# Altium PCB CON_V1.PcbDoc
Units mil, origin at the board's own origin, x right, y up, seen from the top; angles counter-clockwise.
Board outline 3920 x 2000 mil, 2 copper layers (Top Layer, Bottom Layer); 11 components, 18 nets, 80 pads, 4 vias.
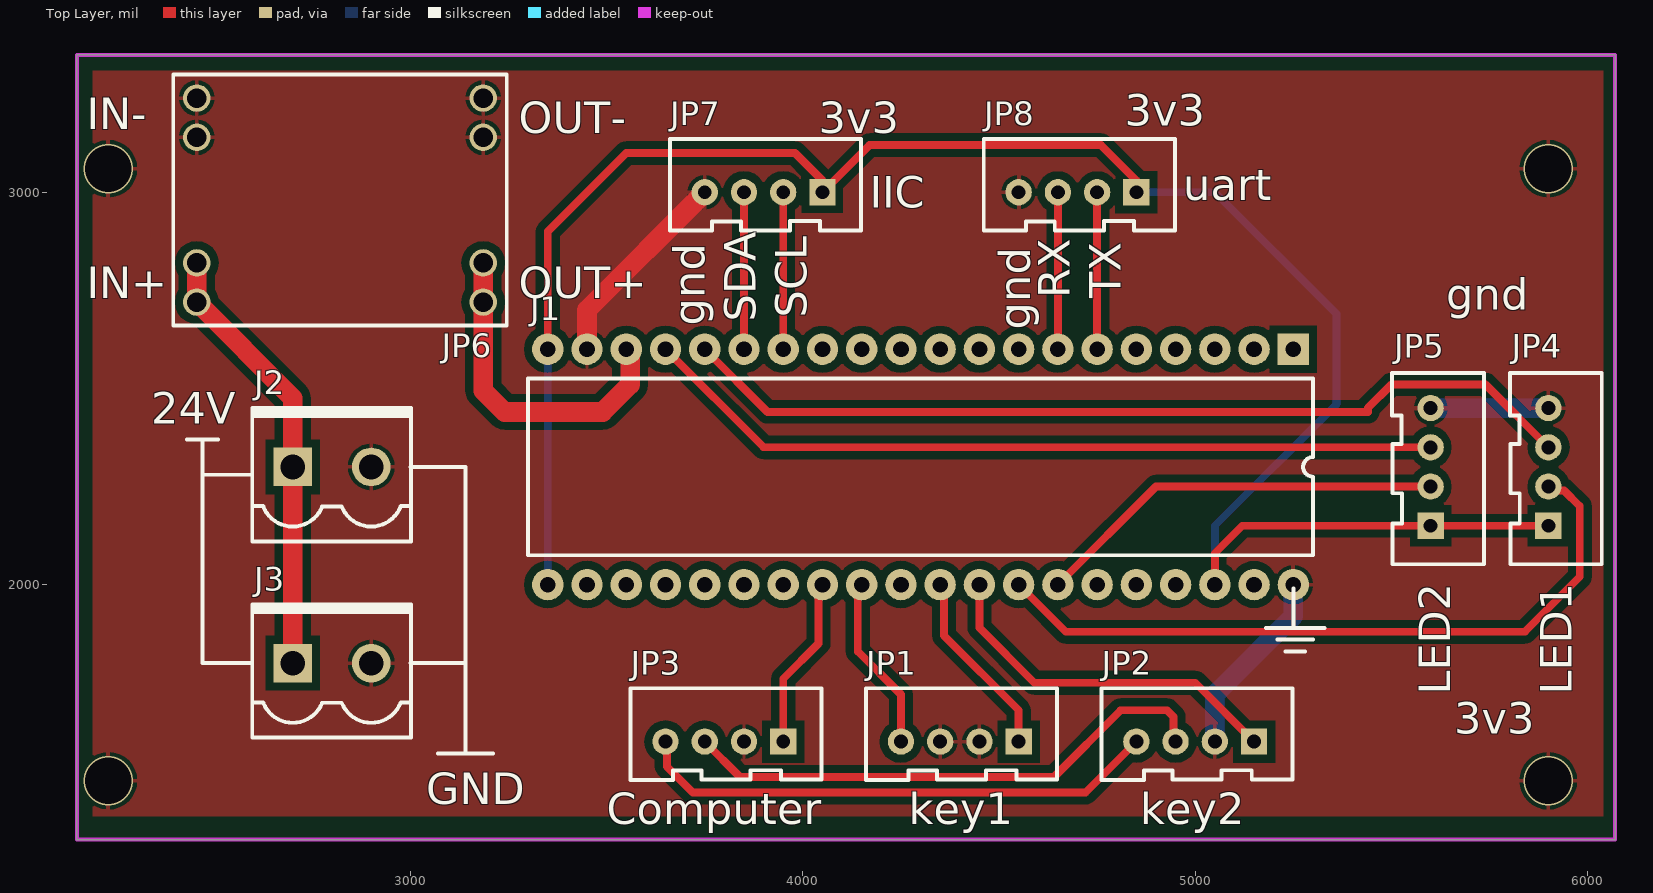
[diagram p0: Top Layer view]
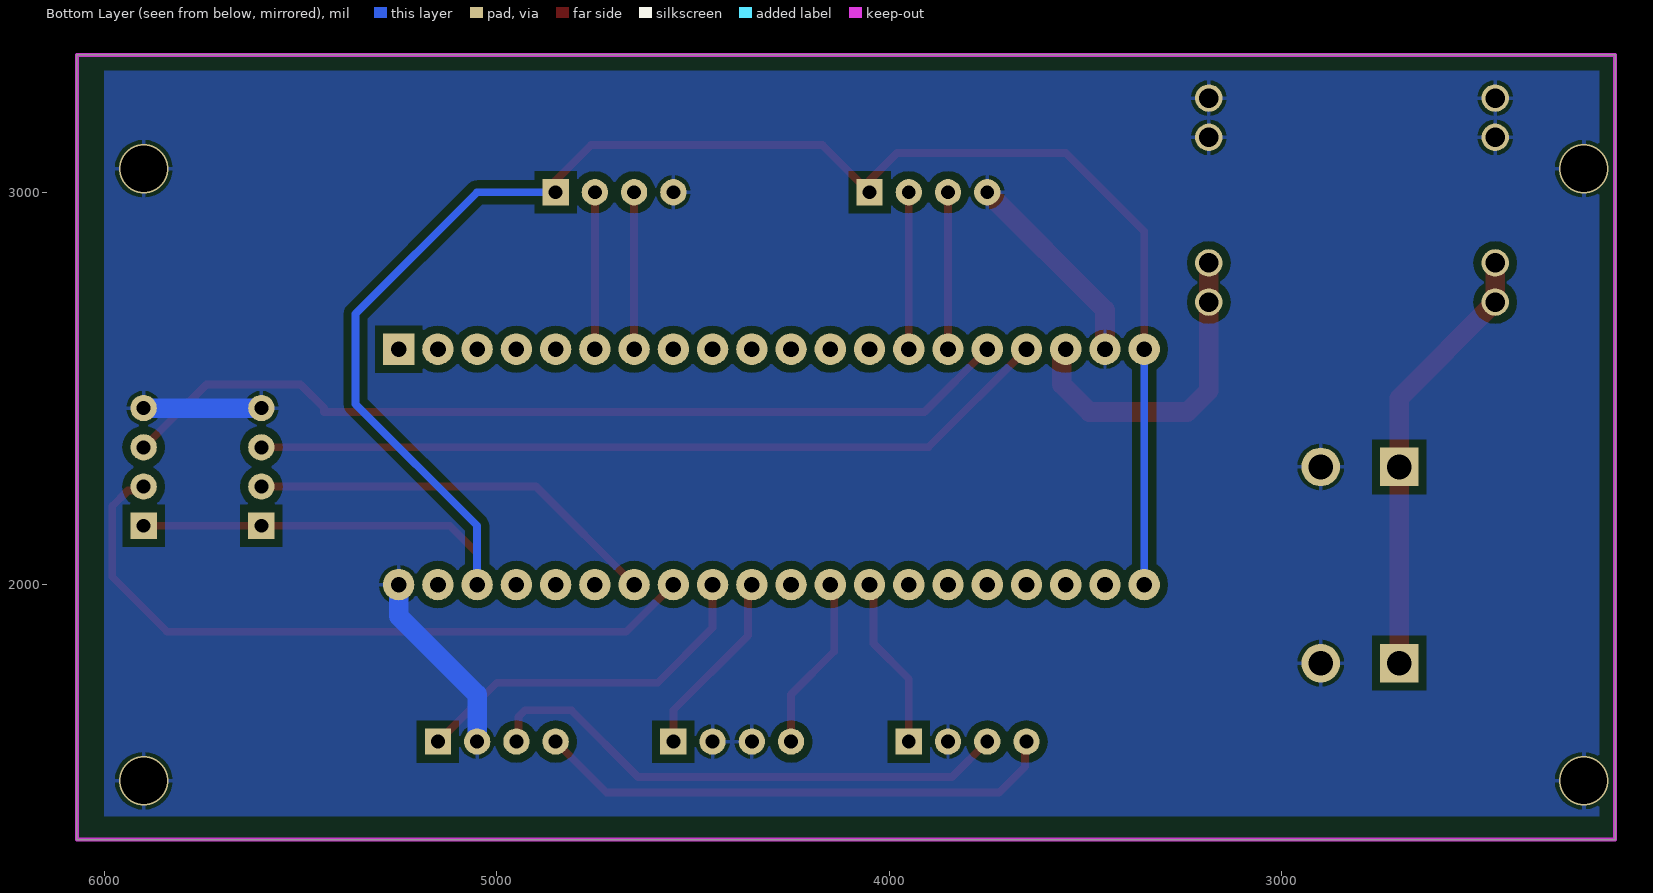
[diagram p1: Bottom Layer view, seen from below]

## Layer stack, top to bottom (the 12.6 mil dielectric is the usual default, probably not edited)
Top Solder: solder mask 0.4, Solder Resist, Dk 3.5
Top Layer: signal copper 1.4
Dielectric 1: dielectric 12.6, FR-4, Dk 4.8
Bottom Layer: signal copper 1.4
Bottom Solder: solder mask 0.4, Solder Resist, Dk 3.5

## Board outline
2150,1350 2150,3350 6070,3350 6070,1350

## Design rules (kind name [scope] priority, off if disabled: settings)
Clearance [All] p1: gap=10 ignorepadtopadclearanceinfootprint=FALSE except(0: Arc-Hole Track-Hole SMDPad-Hole THPad-Hole Via-Hole Fill-Hole Poly-Hole Region-Hole Text-Hole; 20: Arc-Fill Arc-Poly Arc-Region Track-Fill Track-Poly Track-Region SMDPad-Fill SMDPad-Poly SMDPad-Region THPad-Fill THPad-Poly THPad-Region Via-Fill Via-Poly Via-Region Fill-Fill Fill-Poly Fill-Region Poly-Poly Poly-Region Region-Region)
PlaneClearance [All] p1: clearance=30
PolygonConnect [All] p1: connectstyle=Relief reliefconductorwidth=10 reliefentries=4 polygonreliefangle="90 Angle" airgapwidth=10
RoutingVias [All] p1: holewidth=28 width=50 viastyle="Through Hole" minholewidth=28 minwidth=50 maxholewidth=28 maxwidth=50
SolderMaskExpansion [All] p1: expansion=4
Width [All] p1: maxlimit=100 minlimit=10 preferedwidth=20 minimp=50.000000 maximp=50.000000 favimp=50.000000
29 further rules are at their usual default settings.

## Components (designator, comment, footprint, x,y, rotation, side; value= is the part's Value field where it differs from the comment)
J1 "C8T6" C8T6 4300,2300 r270 top
J2 "CON2" KF2EDGK5.08-LI-2P 2800,2300 r0 top
J3 "CON2" KF2EDGK5.08-LI-2P 2800,1800 r0 top
JP1 "HDR-1X4" XH2.54-LI-4P 4400,1600 r180 top
JP2 "HDR-1X4" XH2.54-LI-4P 5000,1600 r180 top
JP3 "HDR-1X4" XH2.54-LI-4P 3800,1600 r180 top
JP4 "HDR-1X4" XH2.54-LI-4P 5900,2300 r90 top
JP5 "HDR-1X4" XH2.54-LI-4P 5600,2300 r90 top
JP6 "Stereye buck module" "Stereye buck module" 2455.47,2720 r0 top
JP7 "HDR-1X4" XH2.54-LI-4P 3900,3000 r180 top
JP8 "HDR-1X4" XH2.54-LI-4P 4700,3000 r180 top

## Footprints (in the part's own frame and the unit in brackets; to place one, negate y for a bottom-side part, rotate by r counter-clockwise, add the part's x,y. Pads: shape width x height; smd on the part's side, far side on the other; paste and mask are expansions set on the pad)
C8T6 [mil]
  rect 80x80 hole 40: 1(-300,950)
  round 80 hole 40: 2(-300,850) 3(-300,750) 4(-300,650) 5(-300,550) 6(-300,450) 7(-300,350) 8(-300,250) 9(-300,150) 10(-300,50) 11(-300,-50) 12(-300,-150) 13(-300,-250) 14(-300,-350) 15(-300,-450) 16(-300,-550) 17(-300,-650) 18(-300,-750) 19(-300,-850) 20(-300,-950) 21(300,-950) 22(300,-850) 23(300,-750) 24(300,-650) 25(300,-550) 26(300,-450) 27(300,-350) 28(300,-250) 29(300,-150) 30(300,-50) 31(300,50) 32(300,150) 33(300,250) 34(300,350) 35(300,450) 36(300,550) 37(300,650) 38(300,750) 39(300,850) 40(300,950)
  silkscreen extent -225,-1000 225,1000
KF2EDGK5.08-LI-2P [mm] "立插端子"
  rect 2.5x2.5 hole 1.6: 1(-2.54,0)
  round 2.5 hole 1.6: 2(2.54,0)
  silkscreen extent -5.16,-4.83 5.13,3.81, body extent -5.08,-4.75 5.08,3.75, height 11.25
"Stereye buck module" [mil]
  round 70 hole 50: 1(0,520) 2(0,420) 3(0,100) 4(0,0) 5(730,0) 6(730,100) 7(730,420) 8(730,520)
  silkscreen extent -60,-60 790,580
XH2.54-LI-4P [mm] "接插件，4P  淘宝ID:黄晶宝石   店铺网址:https://shop463601444.taobao.com"
  rect 1.7x1.7 hole 0.9: 1(-3.81,0)
  round 1.7 hole 0.9: 2(-1.27,0) 3(1.27,0) 4(3.81,0)
  silkscreen extent -6.3,-3.45 6.07,2.49, body extent -6.31,-3.3 6.31,2.4, height 7.03

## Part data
J1: "C8T6转接"
JP1 JP2 JP3 JP4 JP5 JP7 JP8: library part "Header 4", "4P接插件"

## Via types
v1: diameter 125.98, hole 118.11, Top Layer to Bottom Layer, 4 vias

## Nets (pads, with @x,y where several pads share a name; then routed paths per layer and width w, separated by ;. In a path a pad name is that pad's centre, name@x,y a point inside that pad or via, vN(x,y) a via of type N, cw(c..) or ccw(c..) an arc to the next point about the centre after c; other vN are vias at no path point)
3V3: J1.20 J1.21 J1.38 JP4.1 JP5.1 JP7.1 JP8.1 | length 5074.6
  Top Layer w20: J1.20 3350,2900 3550,3100 3980,3100 4050,3030 JP7.1 4170,3120 4760,3120 4850,3030 JP8.1 ; J1.38 5050,2080 5120,2150 JP5.1 JP4.1
  Bottom Layer w20: J1.21 J1.20 ; JP8.1 5050,3000 5360,2690 5360,2460 5050,2150 J1.38
24V: J2.1 J3.1 JP6.3 JP6.4 | length 1121.3
  Top Layer w50: JP6.3 JP6.4 2700,2475.47 J2.1 J3.1
+5: J1.18 JP6.5 JP6.6 | length 845.7
  Top Layer w50: JP6.6 JP6.5 3185.47,2494.53 3240,2440 3490,2440 3560,2510 3560,2590 J1.18
GND: J1.19 J1.40 J2.2 J3.2 JP1.2 JP1.3 JP2.2 JP3.2 JP4.4 JP5.4 JP6.1 JP6.2 JP6.7 JP6.8 JP7.4 JP8.4 | length 1307.1
  Top Layer w50: J1.19 3450,2700 JP7.4
  Bottom Layer w50: JP2.2 5050,1720 5250,1920 J1.40 ; JP5.4 JP4.4
  other v1: 2230,1500 5900,1500 2230,3060 5900,3060
KEY1: J1.29 JP1.4 | length 449.7
  Top Layer w20: J1.29 4140,1990 4140,1830 4250,1720 JP1.4
KEY2: JP2.4 JP3.4 | length 1342.8
  Top Layer w20: JP3.4 3653.46,1596.54 3653.46,1536.54 3720,1470 4720,1470 JP2.4
KEY2_GND: JP2.3 JP3.3 | length 1375
  Top Layer w20: JP3.3 3840,1510 4640,1510 4810,1680 4928.28,1680 4944.82,1663.46 4944.82,1605.18 JP2.3
KEYLED1+: J1.31 JP1.1 | length 482.8
  Top Layer w20: J1.31 4360,1990 4360,1870 4550,1680 JP1.1
KEYLED2+: J1.32 JP2.1 | length 930.1
  Top Layer w20: J1.32 4450,1890 4590,1750 5000,1750 JP2.1
LED1G: J1.16 JP4.3 | length 2317.4
  Top Layer w20: J1.16 3910,2440 5440,2440 5440,2450 5500,2510 5740,2510 JP4.3
LED1R: J1.33 JP4.2 | length 1818.4
  Top Layer w20: J1.33 4670,1880 5840,1880 5980,2020 5980,2200 5940,2240 5910,2240 JP4.2
LED2G: J1.17 JP5.3 | length 2053.6
  Top Layer w20: J1.17 3900,2350 JP5.3
LED2R: J1.34 JP5.2 | length 1053.6
  Top Layer w20: J1.34 4900,2250 JP5.2
RX: J1.7 JP8.3 | length 400
  Top Layer w20: J1.7 JP8.3
SCL: J1.14 JP7.2 | length 400
  Top Layer w20: J1.14 JP7.2
SDA: J1.15 JP7.3 | length 400
  Top Layer w20: J1.15 JP7.3
TX: J1.6 JP8.2 | length 400
  Top Layer w20: J1.6 JP8.2
WAKE_UP: J1.28 JP3.1 | length 441.4
  Top Layer w20: JP3.1 3950,1760 4040,1850 4040,1990 J1.28
pads on no net: J1.1 J1.2 J1.3 J1.4 J1.5 J1.8 J1.9 J1.10 J1.11 J1.12 J1.13 J1.22 J1.23 J1.24 J1.25 J1.26 J1.27 J1.30 J1.35 J1.36 J1.37 J1.39

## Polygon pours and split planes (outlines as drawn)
GND on Top Layer "GND_L01_P000" (solid, remove dead copper, pour order 0): 2190,3310 2190,1410 6040,1410 6040,3310
GND on Bottom Layer "GND_L02_P002" (solid, remove dead copper, pour order 2): 2190,3310 2190,1410 6000,1410 6000,3310

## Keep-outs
Keep-Out Layer:
  the board outline again, w10

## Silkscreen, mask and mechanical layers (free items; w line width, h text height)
Top Overlay:
  lines w10: 2430,2370 2470,2370 ; 2470,2280 2596.85,2280 ; 2510,2370 2470,2370 ; 2590,1800 2470,1800 2470,2370 ; 3000,1800 3140,1800 ; 3000,2300 3140,2300 3140,1570 ; 3070,1570 3210,1570 ; 5180,1890 5330,1890 ; 5210,1860 5300,1860 ; 5230,1830 5280,1830 ; 5250,1890 5250,1990
  text "3v3" at 4820,3170 h80
  text "3v3" at 4040,3150 h80
  text "uart" at 4970,2980 h80
  text "IIC" at 4170,2960 h80
  text "RX" at 4680,2730 h80 r90
  text "TX" at 4810,2730 h80 r90
  text "gnd" at 5640,2700 h80
  text "SCL" at 4010,2680 h80 r90
  text "SDA" at 3880,2670 h80 r90
  text "gnd" at 3750,2660 h80 r90
  text "gnd" at 4580,2650 h80 r90
  text "24V" at 2340,2410 h80
  text "LED2" at 5650,1720 h80 r90
  text "LED1" at 5960,1720 h80 r90
  text "3v3" at 5660,1620 h80
  text "GND" at 3040,1440 h80
  text "Computer" at 3500,1390 h80
  text "key1" at 4270,1390 h80
  text "key2" at 4860,1390 h80

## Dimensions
2150,1350 to 6070,1350 on Mechanical 15
2150,1350 to 2150,3350 on Mechanical 15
